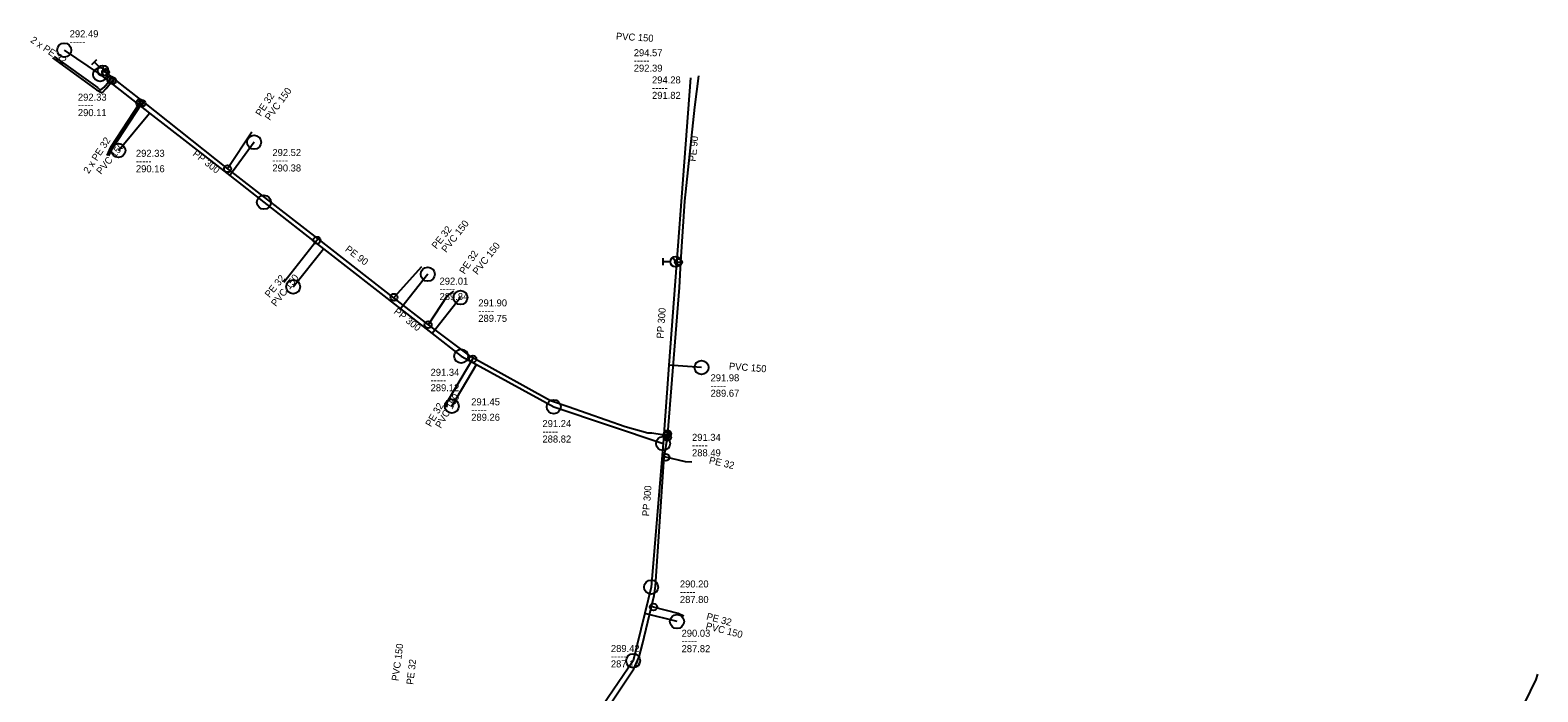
# Model space of a CAD drawing. Extents: x -770828 to -770111, y -1050344 to -1049447.
# Drawn here: x -770618 to -770403.2, y -1049541.6 to -1049447.3 of the extents above; entities that cross this region are included whole.
import ezdxf

# ---------------------------------------------------------------- set-up
doc = ezdxf.new("R2010")
doc.units = 0
doc.layers.add('Level 0', color=7, linetype='Continuous')

msp = doc.modelspace()

# ---------------------------------------------------------------- linework, layer by layer
at = {"layer": 'Level 0'}
for p, q in [((-770613.1, -1049450.15), (-770608, -1049453.63)), ((-770614.77, -1049451.23), (-770608.52, -1049455.79)), ((-770614.52, -1049451.07), (-770608.35, -1049455.47)), ((-770609.18, -1049452.2), (-770608.47, -1049451.49)), ((-770608.12, -1049452.55), (-770608.83, -1049451.84)), ((-770607.68, -1049453.82), (-770607.5, -1049452.33)), ((-770608, -1049453.63), (-770600.96, -1049459.12)), ((-770607.59, -1049453.08), (-770607.22, -1049453.31)), ((-770607.44, -1049455.41), (-770606.5, -1049454.35)), ((-770607.22, -1049453.31), (-770606.25, -1049454.09)), ((-770607.15, -1049455.64), (-770606.22, -1049454.5)), ((-770606.5, -1049454.35), (-770606.25, -1049454.09)), ((-770606.25, -1049454.09), (-770606.01, -1049454.28)), ((-770606.22, -1049454.5), (-770606.01, -1049454.28)), ((-770606.01, -1049454.28), (-770602.09, -1049457.35)), ((-770523.87, -1049454.09), (-770526.95, -1049495.04)), ((-770522.76, -1049453.82), (-770523.33, -1049458.27)), ((-770608.52, -1049455.79), (-770607.7, -1049456.23)), ((-770608.35, -1049455.47), (-770607.95, -1049455.85)), ((-770607.95, -1049455.85), (-770607.44, -1049455.41)), ((-770607.7, -1049456.23), (-770607.15, -1049455.64)), ((-770606.48, -1049464), (-770602.36, -1049457.67)), ((-770606.27, -1049464.2), (-770602.04, -1049457.75)), ((-770602.36, -1049457.67), (-770602.09, -1049457.35)), ((-770602.09, -1049457.35), (-770601.87, -1049457.52)), ((-770602.04, -1049457.75), (-770601.87, -1049457.52)), ((-770601.87, -1049457.52), (-770589.84, -1049467.07)), ((-770523.33, -1049458.27), (-770524.73, -1049471.68)), ((-770605.4, -1049464.46), (-770600.96, -1049459.12)), ((-770600.96, -1049459.12), (-770589.53, -1049468.03)), ((-770586.38, -1049461.83), (-770589.84, -1049467.07)), ((-770606.99, -1049465.17), (-770606.48, -1049464)), ((-770606.77, -1049465.24), (-770606.27, -1049464.2)), ((-770586.04, -1049463.28), (-770589.53, -1049468.03)), ((-770589.84, -1049467.07), (-770576.97, -1049477.07)), ((-770589.53, -1049468.03), (-770584.65, -1049471.84)), ((-770524.73, -1049471.68), (-770525.32, -1049480.32)), ((-770584.65, -1049471.84), (-770576.16, -1049478.47)), ((-770581.84, -1049483.24), (-770577.11, -1049477.24)), ((-770577.11, -1049477.24), (-770576.97, -1049477.07)), ((-770576.97, -1049477.07), (-770566.16, -1049485.52)), ((-770580.49, -1049483.89), (-770576.16, -1049478.47)), ((-770576.16, -1049478.47), (-770565.18, -1049487.03)), ((-770527.75, -1049480.81), (-770527.75, -1049479.81)), ((-770525.54, -1049480.9), (-770526.46, -1049479.72)), ((-770562.2, -1049481.06), (-770566.11, -1049485.37)), ((-770561.32, -1049482.09), (-770565.18, -1049487.03)), ((-770526.75, -1049480.31), (-770527.75, -1049480.31)), ((-770526, -1049480.31), (-770525.59, -1049480.38)), ((-770525.59, -1049480.38), (-770525.32, -1049480.32)), ((-770525.32, -1049480.32), (-770525.51, -1049483.98)), ((-770557.67, -1049484.51), (-770558.56, -1049485.19)), ((-770525.51, -1049483.98), (-770527.14, -1049504.82)), ((-770566.11, -1049485.37), (-770566.16, -1049485.52)), ((-770566.16, -1049485.52), (-770561.26, -1049489.29)), ((-770558.56, -1049485.19), (-770561.26, -1049489.29)), ((-770556.66, -1049485.42), (-770560.68, -1049490.55)), ((-770565.18, -1049487.03), (-770560.68, -1049490.55)), ((-770561.26, -1049489.29), (-770555.58, -1049493.58)), ((-770560.68, -1049490.55), (-770556.55, -1049493.77)), ((-770558.49, -1049500.24), (-770554.9, -1049494.17)), ((-770557.89, -1049500.89), (-770554.39, -1049494.95)), ((-770556.55, -1049493.77), (-770554.39, -1049494.95)), ((-770555.58, -1049493.58), (-770554.81, -1049494.02)), ((-770554.9, -1049494.17), (-770554.81, -1049494.02)), ((-770554.81, -1049494.02), (-770543.82, -1049500.1)), ((-770554.39, -1049494.95), (-770543.37, -1049500.98)), ((-770526.95, -1049495.04), (-770527.79, -1049506.22)), ((-770522.3, -1049495.39), (-770526.95, -1049495.04)), ((-770558.64, -1049501.06), (-770558.49, -1049500.24)), ((-770543.82, -1049500.1), (-770541.33, -1049500.94)), ((-770543.37, -1049500.98), (-770527.79, -1049506.22)), ((-770541.33, -1049500.94), (-770533.2, -1049503.78)), ((-770533.2, -1049503.78), (-770529.95, -1049504.71)), ((-770529.95, -1049504.71), (-770529.39, -1049504.71)), ((-770529.39, -1049504.71), (-770527.93, -1049504.93)), ((-770527.93, -1049504.93), (-770527.3, -1049505.07)), ((-770527.61, -1049508.12), (-770527.14, -1049505.35)), ((-770527.3, -1049505.07), (-770527.13, -1049505.1)), ((-770527.14, -1049504.82), (-770527.13, -1049505.1)), ((-770527.14, -1049505.35), (-770527.13, -1049505.1)), ((-770527.79, -1049506.22), (-770529.49, -1049526.68)), ((-770528.87, -1049526.54), (-770527.61, -1049508.12)), ((-770527.39, -1049508.18), (-770527.61, -1049508.12)), ((-770524.6, -1049508.84), (-770527.39, -1049508.18)), ((-770523.7, -1049508.89), (-770524.6, -1049508.84)), ((-770529.49, -1049526.68), (-770530.4, -1049530.42)), ((-770529.06, -1049527.86), (-770528.87, -1049526.54)), ((-770530.7, -1049534.81), (-770529.44, -1049529.43)), ((-770529.44, -1049529.43), (-770529.06, -1049527.86)), ((-770529.15, -1049529.52), (-770529.44, -1049529.43)), ((-770525.62, -1049530.46), (-770529.15, -1049529.52)), ((-770530.4, -1049530.42), (-770532.05, -1049537.18)), ((-770525.8, -1049531.6), (-770530.4, -1049530.43)), ((-770524.83, -1049530.83), (-770525.62, -1049530.46)), ((-770531.2, -1049536.63), (-770530.7, -1049534.81)), ((-770532.05, -1049537.18), (-770537.74, -1049545.57)), ((-770531.94, -1049538.32), (-770531.2, -1049536.63)), ((-770536.06, -1049544.45), (-770531.94, -1049538.32)), ((-770406.91, -1049547.05), (-770403.37, -1049539.83)), ((-770403.37, -1049539.83), (-770403.15, -1049539.11))]:
    msp.add_line(p, q, dxfattribs=at)
for centre, radius in [((-770613.1, -1049450.15), 1), ((-770607.59, -1049453.08), 0.75), ((-770608, -1049453.63), 1), ((-770607.22, -1049453.31), 0.5), ((-770606.5, -1049454.35), 0.5), ((-770606.22, -1049454.5), 0.5), ((-770602.36, -1049457.67), 0.5), ((-770602.04, -1049457.75), 0.5), ((-770586.06, -1049463.28), 1), ((-770605.4, -1049464.46), 1), ((-770589.84, -1049467.07), 0.5), ((-770584.65, -1049471.84), 1), ((-770577.11, -1049477.24), 0.5), ((-770526, -1049480.31), 0.75), ((-770525.59, -1049480.38), 0.5), ((-770561.32, -1049482.09), 1), ((-770580.49, -1049483.89), 1), ((-770556.66, -1049485.42), 1), ((-770566.11, -1049485.37), 0.5), ((-770561.26, -1049489.29), 0.5), ((-770556.55, -1049493.77), 1), ((-770554.9, -1049494.17), 0.5), ((-770522.3, -1049495.39), 1), ((-770557.89, -1049500.89), 1), ((-770543.37, -1049500.98), 1), ((-770527.79, -1049506.22), 1), ((-770527.3, -1049505.07), 0.5), ((-770527.14, -1049504.82), 0.5), ((-770527.14, -1049505.35), 0.5), ((-770527.39, -1049508.18), 0.5), ((-770529.49, -1049526.68), 1), ((-770529.15, -1049529.52), 0.5), ((-770525.8, -1049531.6), 1), ((-770532.05, -1049537.18), 1)]:
    msp.add_circle(centre, radius, dxfattribs=at)

# ---------------------------------------------------------------- texts
for s, p in [('292.49', (-770612.33, -1049448.32)), ('-----', (-770612.33, -1049449.42)), ('294.57', (-770531.96, -1049451.02)), ('-----', (-770531.96, -1049452.12)), ('292.39', (-770531.96, -1049453.22)), ('294.28', (-770529.36, -1049454.9)), ('292.33', (-770611.16, -1049457.36)), ('-----', (-770529.36, -1049456)), ('291.82', (-770529.36, -1049457.1)), ('-----', (-770611.16, -1049458.46)), ('290.11', (-770611.16, -1049459.56)), ('292.33', (-770602.89, -1049465.36)), ('292.52', (-770583.45, -1049465.25)), ('-----', (-770602.89, -1049466.46)), ('290.16', (-770602.89, -1049467.56)), ('-----', (-770583.45, -1049466.35)), ('290.38', (-770583.45, -1049467.45)), ('-----', (-770559.63, -1049484.67)), ('292.01', (-770559.63, -1049483.57)), ('289.84', (-770559.63, -1049485.77)), ('291.90', (-770554.11, -1049486.68)), ('-----', (-770554.11, -1049487.78)), ('289.75', (-770554.11, -1049488.88)), ('-----', (-770560.91, -1049497.67)), ('291.34', (-770560.91, -1049496.57)), ('291.98', (-770521.02, -1049497.35)), ('289.12', (-770560.91, -1049498.77)), ('-----', (-770521.02, -1049498.45)), ('289.67', (-770521.02, -1049499.55)), ('-----', (-770555.12, -1049501.88)), ('291.45', (-770555.12, -1049500.78)), ('289.26', (-770555.12, -1049502.98)), ('291.24', (-770544.97, -1049503.88)), ('-----', (-770544.97, -1049504.98)), ('288.82', (-770544.97, -1049506.08)), ('291.34', (-770523.66, -1049505.84)), ('-----', (-770523.66, -1049506.94)), ('288.49', (-770523.66, -1049508.04)), ('-----', (-770525.39, -1049527.84)), ('290.20', (-770525.39, -1049526.74)), ('287.80', (-770525.39, -1049528.94)), ('290.03', (-770525.15, -1049533.76)), ('289.42', (-770535.22, -1049535.93)), ('-----', (-770525.15, -1049534.86)), ('287.82', (-770525.15, -1049535.96)), ('-----', (-770535.22, -1049537.03)), ('287.14', (-770535.22, -1049538.13))]:
    msp.add_text(s, height=1, dxfattribs=at).set_placement(p)
for s, rotation, p in [('PVC 150', 356.476, (-770534.52, -1049448.65)), ('2 x PE 32', 325.692, (-770618.02, -1049448.94)), ('PE 32', 56.563, (-770585.11, -1049459.67)), ('PVC 150', 53.694, (-770583.81, -1049460.27)), ('2 x PE 32', 56.941, (-770609.62, -1049467.84)), ('PE 90', 84.04, (-770523.14, -1049466.07)), ('PVC 150', 50.258, (-770607.87, -1049467.95)), ('PP 300', 322.063, (-770594.89, -1049465.1)), ('PE 32', 51.997, (-770560.07, -1049478.58)), ('PVC 150', 51.997, (-770558.68, -1049479.1)), ('PE 90', 322.937, (-770573.18, -1049478.71)), ('PVC 150', 51.917, (-770554.24, -1049482.25)), ('PE 32', 56.634, (-770556.07, -1049482.17)), ('PE 32', 50.528, (-770583.87, -1049485.51)), ('PVC 150', 51.379, (-770582.96, -1049486.78)), ('PP 300', 321.967, (-770566.24, -1049487.58)), ('PP 300', 85.703, (-770527.73, -1049491.29)), ('PVC 150', 355.696, (-770518.43, -1049495.68)), ('PVC 150', 59.492, (-770559.46, -1049504.13)), ('PE 32', 59.399, (-770560.87, -1049503.93)), ('PE 32', 346.691, (-770521.31, -1049509.04)), ('PP 300', 85.25, (-770529.78, -1049516.62)), ('PVC 150', 345.73, (-770521.78, -1049532.65)), ('PE 32', 345.089, (-770521.69, -1049531.29)), ('PVC 150', 82.405, (-770565.49, -1049540.11)), ('PE 32', 83.404, (-770563.38, -1049540.63))]:
    msp.add_text(s, height=1, rotation=rotation, dxfattribs=at).set_placement(p)

doc.saveas('drawing.dxf')
